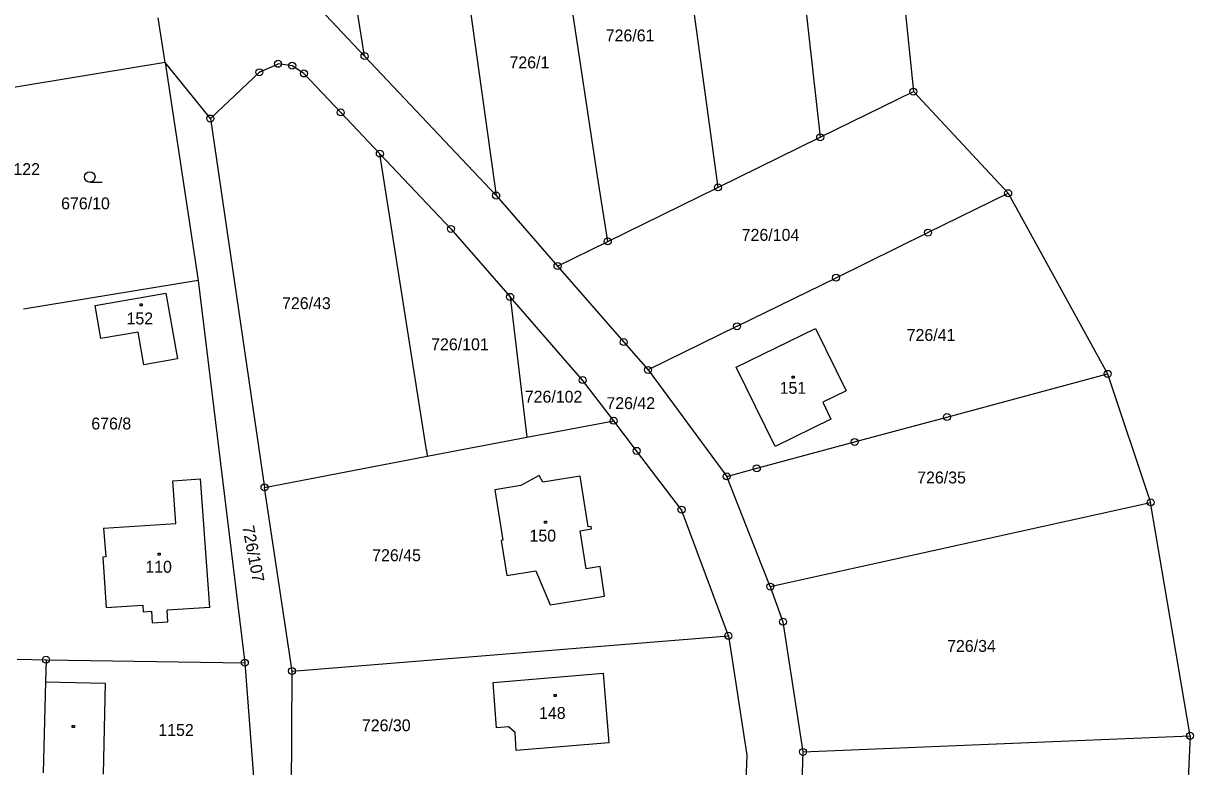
# Model space of a CAD drawing. Extents: x -794142 to -791199, y -1109267 to -1105626.
# Drawn here: x -793312.7 to -793145.7, y -1107745.8 to -1107639.7 of the extents above; entities that cross this region are included whole.
import ezdxf

# ---------------------------------------------------------------- set-up
doc = ezdxf.new("R2010")
doc.units = 0
for name, color, linetype in [('Vrstva 1', 7, 'Continuous'), ('Vrstva 14', 7, 'Continuous'), ('Vrstva 15', 7, 'Continuous'), ('Vrstva 16', 7, 'Continuous'), ('Vrstva 2', 7, 'Continuous'), ('Vrstva 23', 7, 'Continuous'), ('Vrstva 25', 7, 'Continuous'), ('Vrstva 28', 7, 'Continuous')]:
    doc.layers.add(name, color=color, linetype=linetype)

msp = doc.modelspace()

# ---------------------------------------------------------------- linework, layer by layer
at = {"layer": 'Vrstva 1'}
for p, q in [((-793230.76, -1107661.51), (-793237.77, -1107614.9)), ((-793264, -1107644.35), (-793266.51, -1107628.37)), ((-793250.22, -1107628.24), (-793245.22, -1107664.26)), ((-793201.98, -1107629.19), (-793198.96, -1107655.94)), ((-793187.36, -1107632.9), (-793185.66, -1107649.42)), ((-793272.25, -1107635.61), (-793264, -1107644.35)), ((-793217.4, -1107635.09), (-793213.55, -1107663.1)), ((-793292.46, -1107645.29), (-793293.47, -1107638.91)), ((-793292.46, -1107645.29), (-793322.75, -1107650.23)), ((-793292.46, -1107645.29), (-793287.74, -1107676.37)), ((-793286.01, -1107653.27), (-793292.46, -1107645.29)), ((-793279.01, -1107646.66), (-793276.34, -1107645.46)), ((-793274.33, -1107645.73), (-793276.34, -1107645.46)), ((-793272.65, -1107646.84), (-793274.33, -1107645.73)), ((-793264, -1107644.35), (-793245.22, -1107664.26)), ((-793286.01, -1107653.27), (-793279.01, -1107646.66)), ((-793267.4, -1107652.39), (-793272.65, -1107646.84)), ((-793198.96, -1107655.94), (-793185.66, -1107649.42)), ((-793185.66, -1107649.42), (-793172.13, -1107663.93)), ((-793267.4, -1107652.39), (-793261.81, -1107658.3)), ((-793286.01, -1107653.27), (-793278.28, -1107705.93)), ((-793213.55, -1107663.1), (-793198.96, -1107655.94)), ((-793255.17, -1107700.61), (-793261.81, -1107658.3)), ((-793261.81, -1107658.3), (-793251.67, -1107669.03)), ((-793229.28, -1107670.81), (-793230.76, -1107661.51)), ((-793229.28, -1107670.81), (-793213.55, -1107663.1)), ((-793183.58, -1107669.55), (-793172.13, -1107663.93)), ((-793172.13, -1107663.93), (-793157.93, -1107689.72)), ((-793245.22, -1107664.26), (-793236.45, -1107674.33)), ((-793251.67, -1107669.03), (-793243.22, -1107678.73)), ((-793236.45, -1107674.33), (-793229.28, -1107670.81)), ((-793196.69, -1107675.99), (-793183.58, -1107669.55)), ((-793236.45, -1107674.33), (-793227, -1107685.18)), ((-793287.74, -1107676.37), (-793312.7, -1107680.47)), ((-793287.74, -1107676.37), (-793281.09, -1107730.96)), ((-793210.83, -1107682.93), (-793196.69, -1107675.99)), ((-793302.47, -1107679.94), (-793292.36, -1107678.21)), ((-793292.36, -1107678.21), (-793290.69, -1107687.58)), ((-793243.22, -1107678.73), (-793240.82, -1107698.77)), ((-793232.87, -1107690.61), (-793243.22, -1107678.73)), ((-793301.64, -1107684.69), (-793302.47, -1107679.94)), ((-793296.3, -1107683.76), (-793301.64, -1107684.69)), ((-793295.49, -1107688.41), (-793296.3, -1107683.76)), ((-793210.83, -1107682.93), (-793223.53, -1107689.16)), ((-793210.94, -1107688.77), (-793199.61, -1107683.24)), ((-793199.61, -1107683.24), (-793195.27, -1107692.14)), ((-793227, -1107685.18), (-793223.53, -1107689.16)), ((-793290.69, -1107687.58), (-793295.49, -1107688.41)), ((-793223.53, -1107689.16), (-793212.31, -1107704.36)), ((-793205.41, -1107700.09), (-793210.94, -1107688.77)), ((-793228.44, -1107696.41), (-793232.87, -1107690.61)), ((-793180.87, -1107695.89), (-793157.93, -1107689.72)), ((-793157.93, -1107689.72), (-793151.79, -1107708.07)), ((-793195.27, -1107692.14), (-793198.6, -1107693.77)), ((-793198.6, -1107693.77), (-793197.43, -1107696.2)), ((-793194.04, -1107699.44), (-793180.87, -1107695.89)), ((-793240.82, -1107698.77), (-793228.44, -1107696.41)), ((-793225.16, -1107700.71), (-793228.44, -1107696.41)), ((-793197.43, -1107696.2), (-793205.41, -1107700.09)), ((-793255.06, -1107701.49), (-793240.82, -1107698.77)), ((-793255.17, -1107700.61), (-793255.06, -1107701.49)), ((-793218.75, -1107709.11), (-793225.16, -1107700.71)), ((-793208.01, -1107703.2), (-793194.04, -1107699.44)), ((-793278.28, -1107705.93), (-793255.06, -1107701.49)), ((-793239.08, -1107704.21), (-793241.7, -1107705.66)), ((-793238.54, -1107705.17), (-793239.08, -1107704.21)), ((-793212.31, -1107704.36), (-793208.01, -1107703.2)), ((-793291.35, -1107704.97), (-793287.4, -1107704.69)), ((-793290.92, -1107711.08), (-793291.35, -1107704.97)), ((-793286.07, -1107723.05), (-793287.4, -1107704.69)), ((-793274.35, -1107732.14), (-793278.28, -1107705.93)), ((-793241.7, -1107705.66), (-793245.4, -1107706.26)), ((-793233.22, -1107704.32), (-793238.54, -1107705.17)), ((-793232.08, -1107711.56), (-793233.22, -1107704.32)), ((-793207.28, -1107717.07), (-793212.31, -1107704.36)), ((-793245.4, -1107706.26), (-793244.26, -1107713.48)), ((-793212.06, -1107727.11), (-793218.75, -1107709.11)), ((-793206.09, -1107720.09), (-793151.79, -1107708.07)), ((-793146.16, -1107741.39), (-793151.79, -1107708.07)), ((-793301.27, -1107711.77), (-793290.92, -1107711.08)), ((-793301.27, -1107711.77), (-793300.95, -1107715.86)), ((-793233.24, -1107712.13), (-793231.59, -1107711.85)), ((-793232.36, -1107717.56), (-793233.24, -1107712.13)), ((-793231.65, -1107711.49), (-793232.08, -1107711.56)), ((-793231.59, -1107711.85), (-793231.65, -1107711.49)), ((-793244.26, -1107713.48), (-793244.5, -1107713.53)), ((-793244.5, -1107713.53), (-793243.71, -1107718.52)), ((-793300.95, -1107715.86), (-793301.35, -1107715.89)), ((-793301.35, -1107715.89), (-793300.89, -1107723.08)), ((-793230.39, -1107717.2), (-793232.36, -1107717.56)), ((-793229.74, -1107721.47), (-793230.39, -1107717.2)), ((-793206.09, -1107720.09), (-793207.28, -1107717.07)), ((-793243.71, -1107718.52), (-793239.53, -1107717.83)), ((-793239.53, -1107717.83), (-793237.51, -1107722.69)), ((-793206.09, -1107720.09), (-793204.28, -1107725.11)), ((-793237.51, -1107722.69), (-793229.74, -1107721.47)), ((-793300.89, -1107723.08), (-793295.66, -1107722.74)), ((-793295.66, -1107722.74), (-793295.6, -1107723.7)), ((-793295.6, -1107723.7), (-793294.41, -1107723.62)), ((-793294.41, -1107723.62), (-793294.3, -1107725.26)), ((-793286.07, -1107723.05), (-793292.18, -1107723.47)), ((-793292.07, -1107725.12), (-793292.18, -1107723.47)), ((-793294.3, -1107725.26), (-793292.07, -1107725.12)), ((-793204.28, -1107725.11), (-793201.42, -1107743.69)), ((-793274.35, -1107732.14), (-793212.06, -1107727.11)), ((-793212.06, -1107727.11), (-793209.44, -1107744.14)), ((-793313.58, -1107730.47), (-793309.46, -1107730.53)), ((-793309.46, -1107730.53), (-793309.54, -1107733.7)), ((-793309.46, -1107730.53), (-793281.09, -1107730.96)), ((-793281.09, -1107730.96), (-793279.83, -1107747.24)), ((-793274.43, -1107751.19), (-793274.35, -1107732.14)), ((-793245.66, -1107733.77), (-793229.95, -1107732.46)), ((-793229.95, -1107732.46), (-793229.11, -1107742.41)), ((-793309.54, -1107733.7), (-793301.01, -1107733.88)), ((-793301.01, -1107733.88), (-793301.29, -1107746.86)), ((-793245.17, -1107740.23), (-793245.66, -1107733.77)), ((-793243.44, -1107740.13), (-793245.17, -1107740.23)), ((-793242.52, -1107740.91), (-793243.44, -1107740.13)), ((-793242.35, -1107743.51), (-793242.52, -1107740.91)), ((-793229.11, -1107742.41), (-793242.35, -1107743.51)), ((-793201.42, -1107743.69), (-793146.16, -1107741.39)), ((-793146.16, -1107741.39), (-793147.38, -1107766.85)), ((-793209.44, -1107744.14), (-793209.64, -1107749.04)), ((-793201.42, -1107743.69), (-793202.25, -1107765.62))]:
    msp.add_line(p, q, dxfattribs=at)
at = {"layer": 'Vrstva 2'}
msp.add_line((-793309.54, -1107733.7), (-793309.86, -1107746.68), dxfattribs=at)
at = {"layer": 'Vrstva 23'}
msp.add_line((-793303.22, -1107662.36), (-793301.47, -1107662.36), dxfattribs=at)
msp.add_circle((-793303.22, -1107661.61), 0.75, dxfattribs=at)
at = {"layer": 'Vrstva 25'}
for p, q in [((-793296.04, -1107679.73), (-793295.74, -1107679.73)), ((-793296.04, -1107680.03), (-793296.04, -1107679.73)), ((-793295.74, -1107680.03), (-793296.04, -1107680.03)), ((-793295.74, -1107679.73), (-793295.74, -1107680.03)), ((-793202.98, -1107690.04), (-793202.68, -1107690.04)), ((-793202.98, -1107690.34), (-793202.98, -1107690.04)), ((-793202.68, -1107690.34), (-793202.98, -1107690.34)), ((-793202.68, -1107690.04), (-793202.68, -1107690.34)), ((-793238.31, -1107710.73), (-793238.01, -1107710.73)), ((-793238.31, -1107711.03), (-793238.31, -1107710.73)), ((-793238.01, -1107710.73), (-793238.01, -1107711.03)), ((-793238.01, -1107711.03), (-793238.31, -1107711.03)), ((-793293.46, -1107715.32), (-793293.16, -1107715.32)), ((-793293.46, -1107715.62), (-793293.46, -1107715.32)), ((-793293.16, -1107715.62), (-793293.46, -1107715.62)), ((-793293.16, -1107715.32), (-793293.16, -1107715.62)), ((-793236.95, -1107735.5), (-793236.65, -1107735.5)), ((-793236.95, -1107735.8), (-793236.95, -1107735.5)), ((-793236.65, -1107735.8), (-793236.95, -1107735.8)), ((-793236.65, -1107735.5), (-793236.65, -1107735.8)), ((-793305.72, -1107739.9), (-793305.42, -1107739.9)), ((-793305.72, -1107740.2), (-793305.72, -1107739.9)), ((-793305.42, -1107740.2), (-793305.72, -1107740.2)), ((-793305.42, -1107739.9), (-793305.42, -1107740.2))]:
    msp.add_line(p, q, dxfattribs=at)
at = {"layer": 'Vrstva 28'}
for centre, radius in [((-793264, -1107644.35), 0.5), ((-793276.34, -1107645.46), 0.5), ((-793276.34, -1107645.46), 0.01), ((-793274.33, -1107645.73), 0.5), ((-793274.33, -1107645.73), 0.01), ((-793264, -1107644.35), 0.01), ((-793279.01, -1107646.66), 0.5), ((-793279.01, -1107646.66), 0.01), ((-793272.65, -1107646.84), 0.5), ((-793272.65, -1107646.84), 0.01), ((-793185.66, -1107649.42), 0.5), ((-793185.66, -1107649.42), 0.01), ((-793267.4, -1107652.39), 0.5), ((-793267.4, -1107652.39), 0.01), ((-793286.01, -1107653.27), 0.5), ((-793286.01, -1107653.27), 0.01), ((-793198.96, -1107655.94), 0.5), ((-793198.96, -1107655.94), 0.01), ((-793261.81, -1107658.3), 0.5), ((-793261.81, -1107658.3), 0.01), ((-793245.22, -1107664.26), 0.5), ((-793213.55, -1107663.1), 0.5), ((-793213.55, -1107663.1), 0.01), ((-793172.13, -1107663.93), 0.5), ((-793172.13, -1107663.93), 0.01), ((-793245.22, -1107664.26), 0.01), ((-793251.67, -1107669.03), 0.5), ((-793251.67, -1107669.03), 0.01), ((-793183.58, -1107669.55), 0.5), ((-793229.28, -1107670.81), 0.5), ((-793229.28, -1107670.81), 0.01), ((-793183.58, -1107669.55), 0.01), ((-793236.45, -1107674.33), 0.5), ((-793236.45, -1107674.33), 0.01), ((-793196.69, -1107675.99), 0.5), ((-793196.69, -1107675.99), 0.01), ((-793243.22, -1107678.73), 0.5), ((-793243.22, -1107678.73), 0.01), ((-793210.83, -1107682.93), 0.5), ((-793210.83, -1107682.93), 0.01), ((-793227, -1107685.18), 0.5), ((-793227, -1107685.18), 0.01), ((-793223.53, -1107689.16), 0.5), ((-793223.53, -1107689.16), 0.01), ((-793157.93, -1107689.72), 0.5), ((-793232.87, -1107690.61), 0.5), ((-793232.87, -1107690.61), 0.01), ((-793157.93, -1107689.72), 0.01), ((-793228.44, -1107696.41), 0.5), ((-793180.87, -1107695.89), 0.5), ((-793180.87, -1107695.89), 0.01), ((-793228.44, -1107696.41), 0.01), ((-793194.04, -1107699.44), 0.5), ((-793225.16, -1107700.71), 0.5), ((-793225.16, -1107700.71), 0.01), ((-793194.04, -1107699.44), 0.01), ((-793212.31, -1107704.36), 0.5), ((-793208.01, -1107703.2), 0.5), ((-793208.01, -1107703.2), 0.01), ((-793278.28, -1107705.93), 0.5), ((-793278.28, -1107705.93), 0.01), ((-793212.31, -1107704.36), 0.01), ((-793151.79, -1107708.07), 0.5), ((-793218.75, -1107709.11), 0.5), ((-793218.75, -1107709.11), 0.01), ((-793151.79, -1107708.07), 0.01), ((-793206.09, -1107720.09), 0.5), ((-793206.09, -1107720.09), 0.01), ((-793204.28, -1107725.11), 0.5), ((-793204.28, -1107725.11), 0.01), ((-793212.06, -1107727.11), 0.5), ((-793212.06, -1107727.11), 0.01), ((-793309.46, -1107730.53), 0.5), ((-793309.46, -1107730.53), 0.01), ((-793281.09, -1107730.96), 0.5), ((-793281.09, -1107730.96), 0.01), ((-793274.35, -1107732.14), 0.5), ((-793274.35, -1107732.14), 0.01), ((-793146.16, -1107741.39), 0.5), ((-793146.16, -1107741.39), 0.01), ((-793201.42, -1107743.69), 0.5), ((-793201.42, -1107743.69), 0.01)]:
    msp.add_circle(centre, radius, dxfattribs=at)

# ---------------------------------------------------------------- texts
at = {"layer": 'Vrstva 14'}
for s, p in [('726/61', (-793229.57, -1107642.26)), ('726/1', (-793243.31, -1107646.11)), ('676/10', (-793307.309, -1107666.23)), ('726/104', (-793210.164, -1107670.73)), ('726/43', (-793275.772, -1107680.48)), ('726/41', (-793186.615, -1107685.02)), ('726/101', (-793254.492, -1107686.35)), ('726/102', (-793241.128, -1107693.83)), ('726/42', (-793229.482, -1107694.75)), ('676/8', (-793303, -1107697.66)), ('726/35', (-793185.113, -1107705.36)), ('726/45', (-793262.908, -1107716.46)), ('726/34', (-793180.842, -1107729.41)), ('726/30', (-793264.375, -1107740.74)), ('1152', (-793293.439, -1107741.41))]:
    msp.add_text(s, height=1.7, dxfattribs=at).set_placement(p)
msp.add_text('726/107', height=1.7, rotation=280.85292, dxfattribs=at).set_placement((-793281.472, -1107711.521))
at = {"layer": 'Vrstva 15'}
for s, p in [('152', (-793297.976, -1107682.66)), ('151', (-793204.749, -1107692.57)), ('150', (-793240.455, -1107713.66)), ('110', (-793295.292, -1107718.11)), ('148', (-793239.086, -1107738.98))]:
    msp.add_text(s, height=1.7, dxfattribs=at).set_placement(p)
at = {"layer": 'Vrstva 16'}
msp.add_text('122', height=1.7, dxfattribs=at).set_placement((-793314.12, -1107661.34))

doc.saveas('drawing.dxf')
